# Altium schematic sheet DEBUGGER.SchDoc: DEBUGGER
size A3; Author: Arturo Guadalupi; CompanyName: Arduino srl; DocumentNumber: ABX00043; SheetNumber: 3; SheetTotal: 14; RevAuthor: S. Navaretti
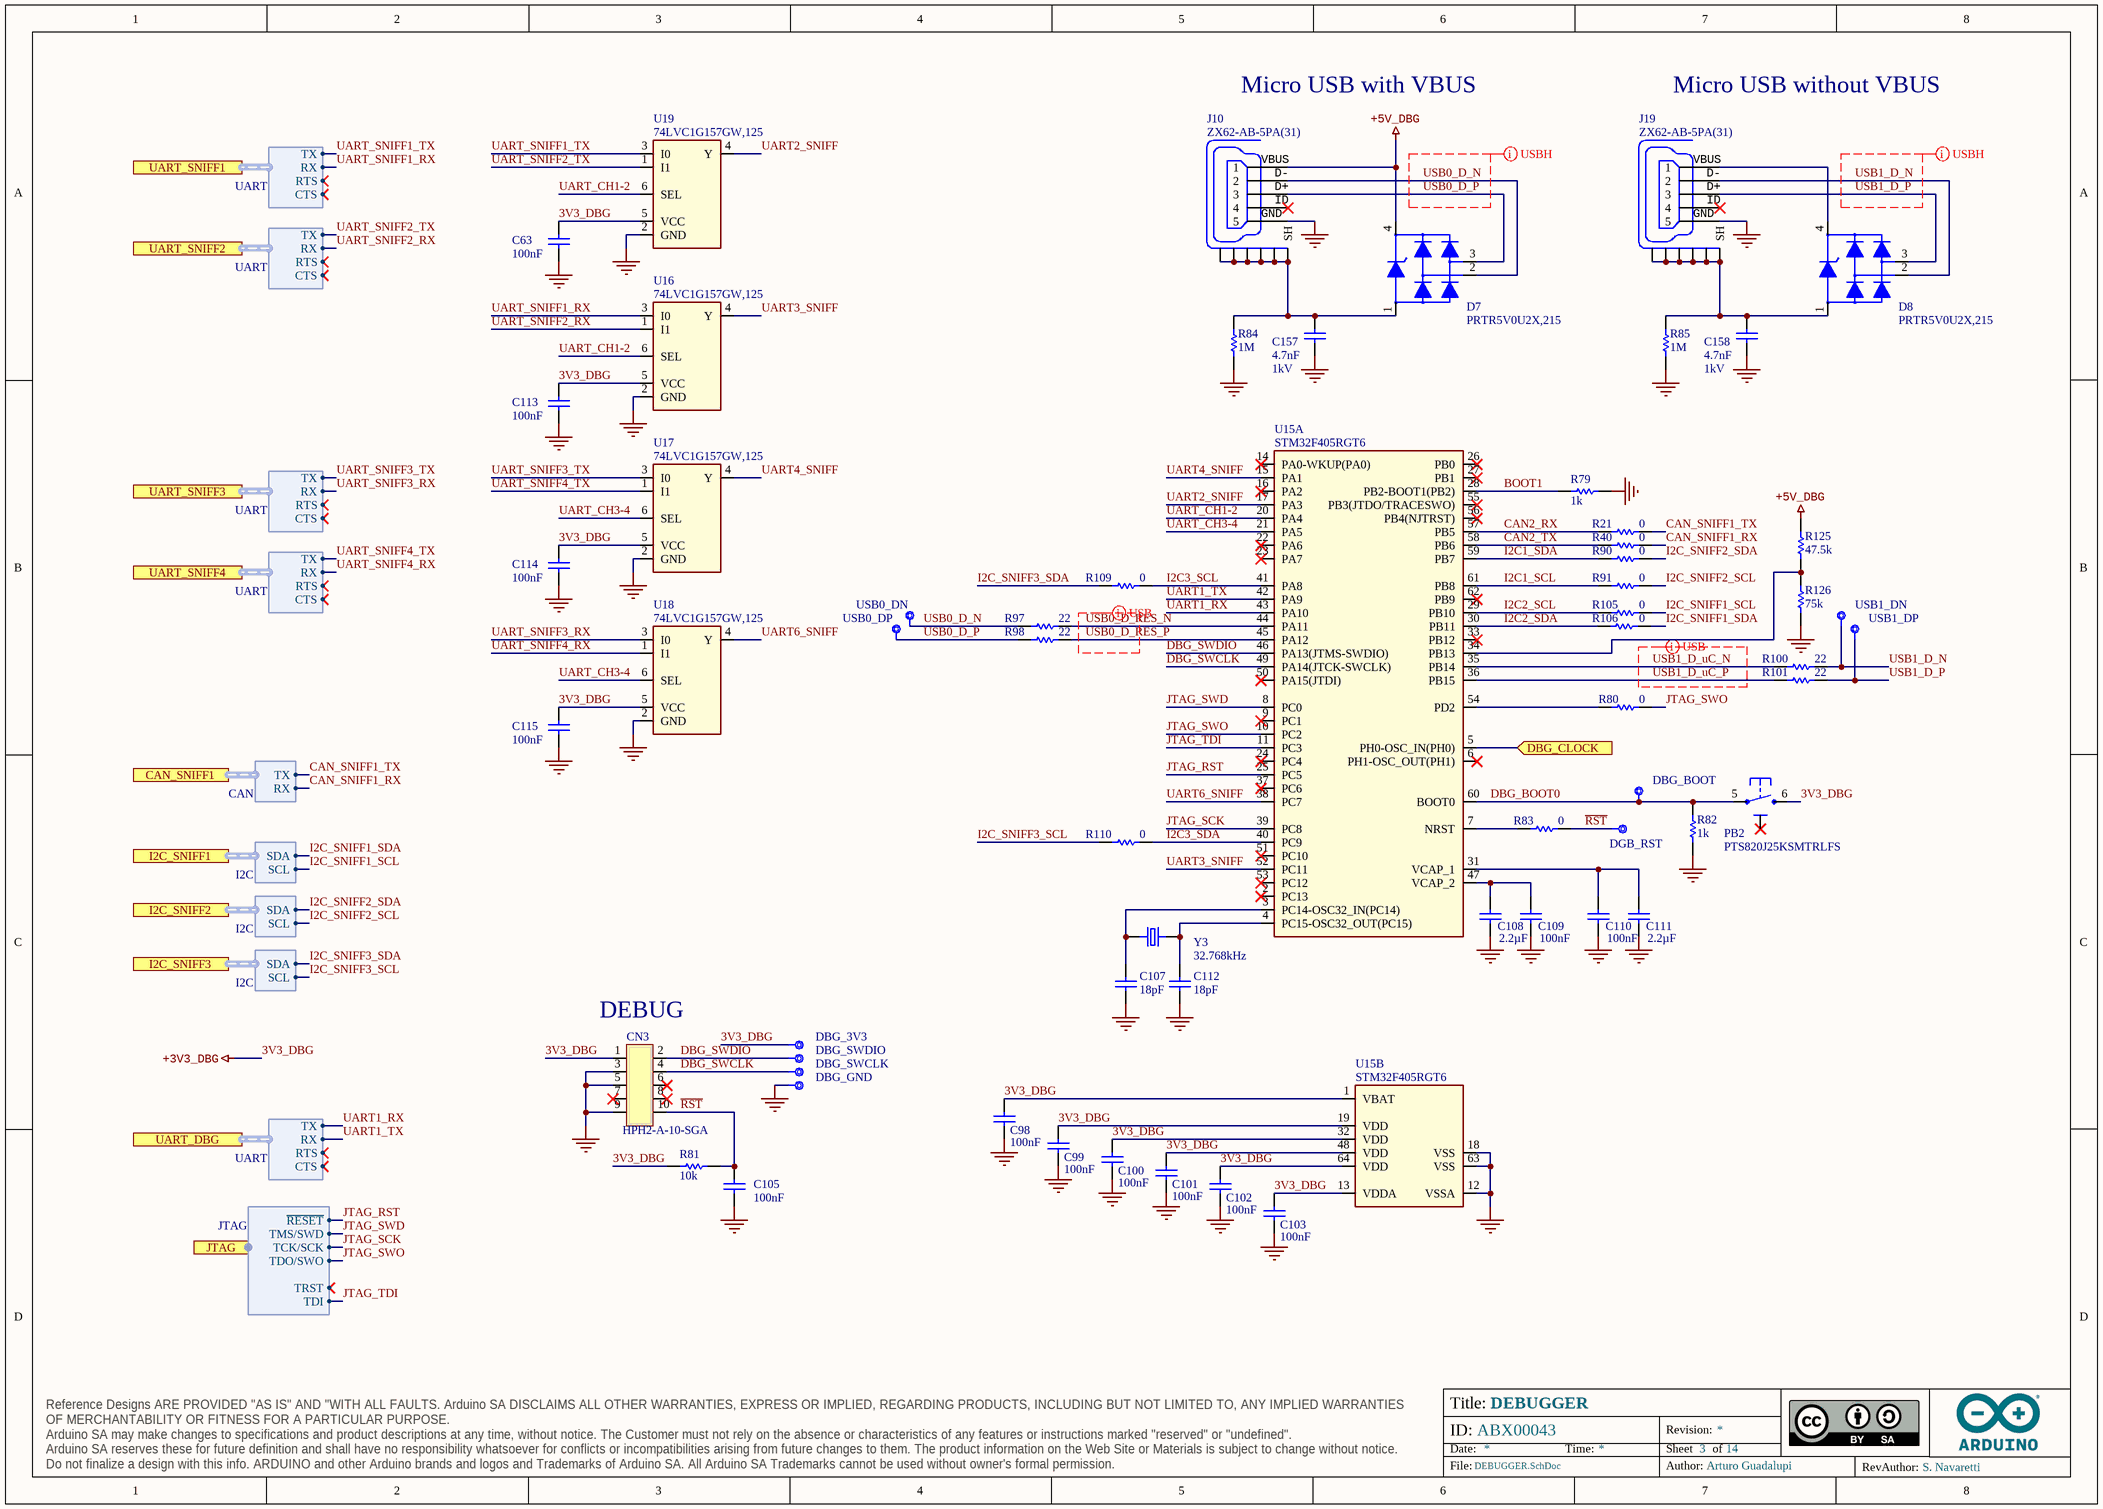
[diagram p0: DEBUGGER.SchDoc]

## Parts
C63  value 100nF  [CAP-0402]  (hidden comment: C0402C104K4RACTU)
C98  value 100nF  [CAP-0402]  (hidden comment: C0402C104K4RACTU)
C99  value 100nF  [CAP-0402]  (hidden comment: C0402C104K4RACTU)
C100  value 100nF  [CAP-0402]  (hidden comment: C0402C104K4RACTU)
C101  value 100nF  [CAP-0402]  (hidden comment: C0402C104K4RACTU)
C102  value 100nF  [CAP-0402]  (hidden comment: C0402C104K4RACTU)
C103  value 100nF  [CAP-0402]  (hidden comment: C0402C104K4RACTU)
C105  value 100nF  [CAP-0402]  (hidden comment: C0402C104K4RACTU)
C107  value 18pF  [CAP-0402]  (hidden comment: C0402C180J5GACTU)
C108  value 2.2µF  [CAP-0402]  (hidden comment: GRM155R60J225KE95D)
C109  value 100nF  [CAP-0402]  (hidden comment: C0402C104K4RACTU)
C110  value 100nF  [CAP-0402]  (hidden comment: C0402C104K4RACTU)
C111  value 2.2µF  [CAP-0402]  (hidden comment: GRM155R60J225KE95D)
C112  value 18pF  [CAP-0402]  (hidden comment: C0402C180J5GACTU)
C113  value 100nF  [CAP-0402]  (hidden comment: C0402C104K4RACTU)
C114  value 100nF  [CAP-0402]  (hidden comment: C0402C104K4RACTU)
C115  value 100nF  [CAP-0402]  (hidden comment: C0402C104K4RACTU)
C157  value 4.7nF  Voltage: 1kV  [CAP-0805]  (hidden comment: C0805C472KDRACTU)
C158  value 4.7nF  Voltage: 1kV  [CAP-0805]  (hidden comment: C0805C472KDRACTU)
CN3  HPH2-A-10-SGA  [PINHEAD_2X05_127]
D7  PRTR5V0U2X,215  [SOT190P230X110-4N]
D8  PRTR5V0U2X,215  [SOT190P230X110-4N]
DBG_3V3  CMP-018-0005-A.3  [TP-1.00MM]  (value not drawn)  (no BOM)
DBG_BOOT  CMP-018-0005-A.3  [TP-1.00MM]  (value not drawn)  (no BOM)
DBG_GND  CMP-018-0005-A.3  [TP-1.00MM]  (value not drawn)  (no BOM)
DBG_SWCLK  CMP-018-0005-A.3  [TP-1.00MM]  (value not drawn)  (no BOM)
DBG_SWDIO  CMP-018-0005-A.3  [TP-1.00MM]  (value not drawn)  (no BOM)
DGB_RST  CMP-018-0005-A.3  [TP-1.00MM]  (value not drawn)  (no BOM)
J10  ZX62-AB-5PA(31)  [ZX62-AB-5PA]
J19  ZX62-AB-5PA(31)  [ZX62-AB-5PA]
PB2  PTS820J25KSMTRLFS  [C&K_PTS820_NO_HOLES-1]
R21  value 0  [RES-0402]  (hidden comment: CRCW04020000Z0EDC)
R40  value 0  [RES-0402]  (hidden comment: CRCW04020000Z0EDC)
R79  value 1k  [RES-0402]  (hidden comment: CRCW04021K00FKEDC)
R80  value 0  [RES-0402]  (hidden comment: CRCW04020000Z0EDC)
R81  value 10k  [RES-0402]  (hidden comment: CRCW040210K0FKED)
R82  value 1k  [RES-0402]  (hidden comment: CRCW04021K00FKEDC)
R83  value 0  [RES-0402]  (hidden comment: CRCW04020000Z0EDC)
R84  value 1M  [RES-0402]  (hidden comment: CRCW04021M00FKED)
R85  value 1M  [RES-0402]  (hidden comment: CRCW04021M00FKED)
R90  value 0  [RES-0402]  (hidden comment: CRCW04020000Z0EDC)
R91  value 0  [RES-0402]  (hidden comment: CRCW04020000Z0EDC)
R97  value 22  [RES-0402]  (hidden comment: RC0402FR-0722RL)
R98  value 22  [RES-0402]  (hidden comment: RC0402FR-0722RL)
R100  value 22  [RES-0402]  (hidden comment: RC0402FR-0722RL)
R101  value 22  [RES-0402]  (hidden comment: RC0402FR-0722RL)
R105  value 0  [RES-0402]  (hidden comment: CRCW04020000Z0EDC)
R106  value 0  [RES-0402]  (hidden comment: CRCW04020000Z0EDC)
R109  value 0  [RES-0402]  (hidden comment: CRCW04020000Z0EDC)
R110  value 0  [RES-0402]  (hidden comment: CRCW04020000Z0EDC)
R125  value 47.5k  [RES-0402]  (hidden comment: CRCW040247K5FKED)
R126  value 75k  [RES-0402]  (hidden comment: CRCW040275K0FKED)
U15  STM32F405RGT6  [STM-LQFP64_M]  (parts A,B of 2)
U16  74LVC1G157GW,125  [TSOP95P280X110-6N]
U17  74LVC1G157GW,125  [TSOP95P280X110-6N]
U18  74LVC1G157GW,125  [TSOP95P280X110-6N]
U19  74LVC1G157GW,125  [TSOP95P280X110-6N]
USB0_DN  CMP-018-0005-A.3  [TP-1.00MM]  (value not drawn)  (no BOM)
USB0_DP  CMP-018-0005-A.3  [TP-1.00MM]  (value not drawn)  (no BOM)
USB1_DN  CMP-018-0005-A.3  [TP-1.00MM]  (value not drawn)  (no BOM)
USB1_DP  CMP-018-0005-A.3  [TP-1.00MM]  (value not drawn)  (no BOM)
Y3  Frequency: 32.768kHz  [ABS07]  (hidden comment: CM315D32768DZFT)

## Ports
CAN_SNIFF1 (harness CAN), DBG_CLOCK (in), I2C_SNIFF1 (harness I2C), I2C_SNIFF2 (harness I2C), I2C_SNIFF3 (harness I2C), JTAG (harness JTAG), UART_DBG (harness UART), UART_SNIFF1 (harness UART), UART_SNIFF2 (harness UART), UART_SNIFF3 (harness UART), UART_SNIFF4 (harness UART)

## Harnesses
UART: RX, TX, RTS, CTS
I2C: SCL, SDA
CAN: RX, TX
JTAG: ~{RESET}, TCK/SCK, TDI, TDO/SWO, TMS/SWD, TRST

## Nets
3V3_DBG: C63.1 C98.2 C99.2 C100.2 C101.2 C102.2 C103.2 C113.1 C114.1 C115.1 CN3.1 DBG_3V3.X PB2.6 R81.2 U15.1(VBAT) U15.13(VDDA) U15.19(VDD) U15.32(VDD) U15.48(VDD) U15.64(VDD) U16.5(VCC) U17.5(VCC) U18.5(VCC) U19.5(VCC)  [also labelled +3V3_DBG]
+5V_DBG: D7.4 J10.1 R125.1
GND: C63.2 C98.1 C99.1 C100.1 C101.1 C102.1 C103.1 C105.1 C107.2 C108.1 C109.1 C110.1 C111.1 C112.2 C113.2 C114.2 C115.2 C157.1 C158.1 CN3.3 CN3.5 CN3.9 DBG_GND.X J10.5 J19.5 R79.1 R82.1 R84.1 R85.1 R126.2 U15.12(VSSA) U15.18(VSS) U15.63(VSS) U16.2(GND) U17.2(GND) U18.2(GND) U19.2(GND)
~{RST}: C105.2 CN3.10 DGB_RST.X R81.1 R83.2
BOOT1: R79.2 U15.28(PB2-BOOT1(PB2))
CAN2_RX: R21.1 U15.57(PB5)
CAN2_TX: R40.1 U15.58(PB6)
CAN_SNIFF1_RX: R40.2 ; port CAN_SNIFF1.RX
CAN_SNIFF1_TX: R21.2 ; port CAN_SNIFF1.TX
DBG_BOOT0: DBG_BOOT.X PB2.5 R82.2 U15.60(BOOT0)
DBG_CLOCK: U15.5(PH0-OSC_IN(PH0)) ; port DBG_CLOCK
DBG_SWCLK: CN3.4 DBG_SWCLK.X U15.49(PA14(JTCK-SWCLK))
DBG_SWDIO: CN3.2 DBG_SWDIO.X U15.46(PA13(JTMS-SWDIO))
I2C1_SCL: R91.1 U15.61(PB8)
I2C1_SDA: R90.1 U15.59(PB7)
I2C2_SCL: R105.1 U15.29(PB10)
I2C2_SDA: R106.1 U15.30(PB11)
I2C3_SCL: R109.2 U15.41(PA8)
I2C3_SDA: R110.2 U15.40(PC9)
I2C_SNIFF1_SCL: R105.2 ; port I2C_SNIFF1.SCL
I2C_SNIFF1_SDA: R106.2 ; port I2C_SNIFF1.SDA
I2C_SNIFF2_SCL: R91.2 ; port I2C_SNIFF2.SCL
I2C_SNIFF2_SDA: R90.2 ; port I2C_SNIFF2.SDA
I2C_SNIFF3_SCL: R110.1 ; port I2C_SNIFF3.SCL
I2C_SNIFF3_SDA: R109.1 ; port I2C_SNIFF3.SDA
JTAG_RST: U15.25(PC5) ; port JTAG.~{RESET}
JTAG_SCK: U15.39(PC8) ; port JTAG.TCK/SCK
JTAG_SWD: U15.8(PC0) ; port JTAG.TMS/SWD
JTAG_SWO: R80.2 U15.10(PC2) ; port JTAG.TDO/SWO
JTAG_TDI: U15.11(PC3) ; port JTAG.TDI
UART1_RX: U15.43(PA10) ; port UART_DBG.TX
UART1_TX: U15.42(PA9) ; port UART_DBG.RX
UART2_SNIFF: U15.17(PA3) U19.4(Y)
UART3_SNIFF: U15.52(PC11) U16.4(Y)
UART4_SNIFF: U15.15(PA1) U17.4(Y)
UART6_SNIFF: U15.38(PC7) U18.4(Y)
UART_CH1-2: U15.20(PA4) U16.6(SEL) U19.6(SEL)
UART_CH3-4: U15.21(PA5) U17.6(SEL) U18.6(SEL)
UART_SNIFF1_RX: U16.3(I0) ; port UART_SNIFF1.RX
UART_SNIFF1_TX: U19.3(I0) ; port UART_SNIFF1.TX
UART_SNIFF2_RX: U16.1(I1) ; port UART_SNIFF2.RX
UART_SNIFF2_TX: U19.1(I1) ; port UART_SNIFF2.TX
UART_SNIFF3_RX: U18.3(I0) ; port UART_SNIFF3.RX
UART_SNIFF3_TX: U17.3(I0) ; port UART_SNIFF3.TX
UART_SNIFF4_RX: U18.1(I1) ; port UART_SNIFF4.RX
UART_SNIFF4_TX: U17.1(I1) ; port UART_SNIFF4.TX
USB0_D_N: D7.2 J10.2 R97.1 USB0_DN.X
USB0_D_P: D7.3 J10.3 R98.1 USB0_DP.X
USB0_D_RES_N: R97.2 U15.44(PA11)
USB0_D_RES_P: R98.2 U15.45(PA12)
USB1_D_N: D8.2 J19.2 R100.2 USB1_DN.X
USB1_D_P: D8.3 J19.3 R101.2 USB1_DP.X
USB1_D_uC_N: R100.1 U15.35(PB14)
USB1_D_uC_P: R101.1 U15.36(PB15)
NetC107_1: C107.1 U15.3(PC14-OSC32_IN(PC14)) Y3.2
NetC108_2: C108.2 C109.2 U15.47(VCAP_2)
NetC110_2: C110.2 C111.2 U15.31(VCAP_1)
NetC112_1: C112.1 U15.4(PC15-OSC32_OUT(PC15)) Y3.1
NetC157_2: C157.2 D7.1 J10.M1(SH) J10.M2(SH) J10.M3(SH) J10.M4(SH) J10.M5(SH) J10.M6(SH) R84.2
NetC158_2: C158.2 D8.1 J19.M1(SH) J19.M2(SH) J19.M3(SH) J19.M4(SH) J19.M5(SH) J19.M6(SH) R85.2
NetD8_4: D8.4 J19.1
NetR80_1: R80.1 U15.54(PD2)
NetR83_1: R83.1 U15.7(NRST)
NetR125_2: R125.2 R126.1 U15.34(PB13)

Not connected (* = marked no-connect by the designer): CN3 6* 7* 8*; J10 4*; J19 4*; PB2 PAD*; U15 2(PC13)* 6(PH1-OSC_OUT(PH1))* 9(PC1)* 14(PA0-WKUP(PA0))* 16(PA2)* 22(PA6)* 23(PA7)* 24(PC4)* 26(PB0)* 27(PB1)* 33(PB12)* 37(PC6)* 50(PA15(JTDI))* 51(PC10)* 53(PC12)* 55(PB3(JTDO/TRACESWO))* 56(PB4(NJTRST))* 62(PB9)*

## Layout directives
differential pair; differential pair class USB: USB0_D_N, USB0_D_P, USB0_D_RES_N, USB0_D_RES_P, USB1_D_N, USB1_D_P, USB1_D_uC_N, USB1_D_uC_P

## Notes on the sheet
- Micro USB with VBUS
- Micro USB without VBUS
- (near CN3) DEBUG

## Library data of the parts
C63 C98-C103 C105 C109 C110 C113-C115 = C0012-A.9: CAP CHIP 0402 100nF 16V X7R 10%; Manufacturer: KEMET; Code Arduino: 0132
C107 C112 = C0026-A.11: CAP CHIP 0402 18pF C0G 50V 5%; Manufacturer: KEMET; Code Arduino: 2320
C108 C111 = C0031-A.9: CAP CHIP 0402 2.2uF 6.3V X5R 10%; Manufacturer: Murata; Code Arduino: A5529
C157 C158 = C0059-A.9: CAP CHIP 0805 4.7nF 1000V X7R 10%; Manufacturer: KEMET; Code Arduino: 0689
CN3 = J0068-A.5: CONN CONN STRIP THD 1,27 M/2/D 10v AuF H6,3 JTAG; Manufacturer: Adam Tech; Code Arduino: 0171
D7 D8 = D0025-A.3: TVS ARRAY 4LIN.8kV 1pF SOT143B; Manufacturer: Nexperia; Device Type: ESD protection; Code Arduino: 2209
DBG_3V3 DBG_BOOT DBG_GND DBG_SWCLK DBG_SWDIO DGB_RST USB0_DN USB0_DP USB1_DN USB1_DP = UT0013-A.2: Test point 1.00mm
J10 J19 = J0039-A.7: CONN USB MICRO F/90^ SMD TipoAB 5x1; Manufacturer: Hirose; Code Arduino: 2219
PB2 = B0006-A.6: PUSHBUTTON SMD PTS820 NO HOLES; Manufacturer: C&K; Mechanical Life: 100000Cycles; Code Arduino: A5506; Actuator Type: Standard
R21 R40 R80 R83 R90 R91 R105 R106 R109 R110 = R0000-A.5: RES CHIP 0402 0R 1/16W; Manufacturer: Vishay; Code Arduino: 0039; Power: 63mW; Tolerance: J
R79 R82 = R0007-A.5: RES CHIP 0402 1K 1% 1/16W; Manufacturer: Vishay; Code Arduino: 0140; Power: 63mW
R81 = R0003-A.5: RES CHIP 0402 10K 1% 1/16W; Manufacturer: Vishay; Code Arduino: 0136; Power: 63mW
R84 R85 = R0058-A.5: RES CHIP 0402 1M 1% 1/16W; Manufacturer: Vishay; Code Arduino: 0139; Power: 63mW
R97 R98 R100 R101 = R0009-A.5: RES CHIP 0402 22R 1% 1/16W; Manufacturer: Yageo; Power: 63mW; Code Arduino: 0468
R125 = R0076-A.16: RES CHIP 0402 47k5 1% 1/16W; Manufacturer: Vishay; Code Arduino: R0076; Power: 63mW
R126 = R0037-A.16: RES CHIP 0402 75k 1% 1/16W; Manufacturer: Yageo; Power: 63mW; Code Arduino: A5480; Tolerance: 5%
U15 = U0118-A.4: MCU 32-bit STM32F ARM Cortex M4F RISC 1024KB Flash 2.5V/3.3V 64-Pin LQFP Tray; Manufacturer: ST Microelectronics; Interface: I2C,SPI,USB,CAN,IrDA,UART,USART,LIN,I2S; Min Supply Voltage: 1.8V; Number of Timers/Counters: 14; Data Bus Width: 32b; Number of SPI Channels: 3; Number of Programmable I/O: 51; Watchdog Timer: Yes; Oscillator Type: Internal; Number of ADC Channels: 16; Peripherals: Brown-out Detect/Reset,POR,PWM,WDT,DMA,LCD,I2C; RAM Size: 196KB; Number of UART Channels: 2; Max Frequency: 168MHz; Code Arduino: U0118; Max Supply Voltage: 3.6V
U16-U19 = U0119-A.4: IC SINGLE 2-INPUT MUX 6TSSOP; Manufacturer: Nexperia; Max Supply Voltage: 5.5V; Min Supply Voltage: 1.65V; Code Arduino: U0119
Y3 = X0003-A.4: CRYSTAL 32.768kHz 20ppm 12.5pF SMD 1.6x0.9mm; Manufacturer: Citizen FineDevice; Code Arduino: 0213; Series Resistance: 70kR; Frequency Stability: 0.12%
